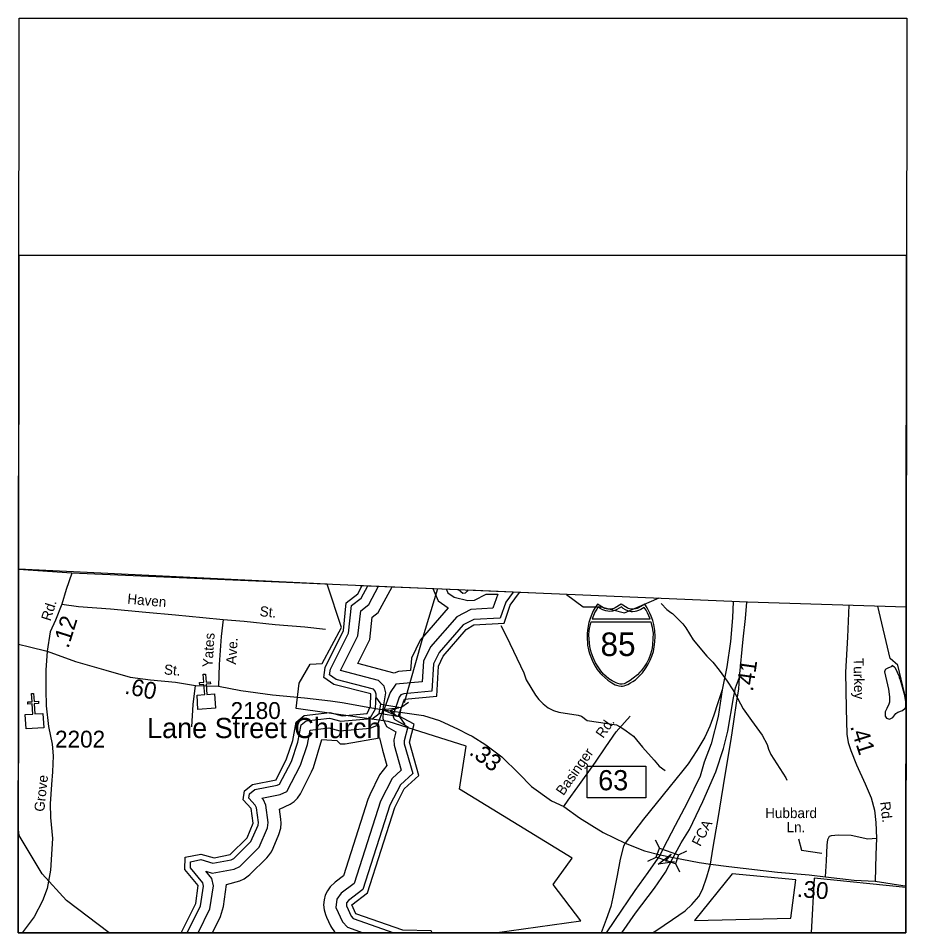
# Model space of a CAD drawing. Extents: x 1513414 to 1532852, y 643392 to 657912.
# Drawn here: x 1513414 to 1520009, y 643669 to 650461 of the extents above; entities that cross this region are included whole.
import ezdxf

# ---------------------------------------------------------------- set-up
doc = ezdxf.new("R2010")
doc.units = 0
doc.layers.add('Default', color=7, linetype='Continuous')

msp = doc.modelspace()

# ---------------------------------------------------------------- linework, layer by layer
at = {"layer": 'Default'}
for p, q in [((1520007.5, 648700.2), (1513418.3, 648700.2)), ((1516681.5, 646215.8), (1515951, 646246.8)), ((1517202.2, 646193.8), (1516751, 646212.9)), ((1516065.3, 645422.1), (1516105.4, 645366)), ((1516254.4, 645340.8), (1516310.5, 645380.9)), ((1516037.6, 645256.2), (1516093.8, 645296.3)), ((1516243, 645272.7), (1516283.1, 645216.6)), ((1518142.8, 644359.3), (1518172.9, 644297.2)), ((1518315.6, 644247.4), (1518377.7, 644277.5)), ((1518087.8, 644200.4), (1518149.8, 644230.5)), ((1518293, 644182.2), (1518323.2, 644120.2))]:
    msp.add_line(p, q, dxfattribs=at)
for points in [[(1513419.9, 650460.8), (1520009.1, 650460.8), (1520002.8, 643669.3), (1513413.6, 643669.3)], [(1517888.8, 645500.4), (1517898.3, 645501.3), (1517911.1, 645503.7), (1517923.4, 645507.8), (1517937.6, 645514), (1517958.4, 645525.6), (1517975.1, 645535.4), (1517994.5, 645548.4), (1518020.6, 645572.1), (1518046.6, 645599.5), (1518069.6, 645630.6), (1518087.9, 645659.6), (1518104, 645692.7), (1518117.4, 645723.6), (1518128.1, 645759), (1518135.1, 645793.2), (1518138.7, 645828.9), (1518141.1, 645868.5), (1518138.4, 645913), (1518130.6, 645958.6), (1518123.4, 645986.9), (1518112.3, 646020.9), (1518103.3, 646042.6), (1518082.5, 646081), (1518063.8, 646110.6), (1518036.5, 646091.4), (1518018.8, 646082), (1518007.9, 646077.1), (1517996.8, 646074.9), (1517976.3, 646072.4), (1517963.4, 646073), (1517951.4, 646075.7), (1517941.3, 646077.9), (1517933.1, 646082), (1517888.8, 646110.6), (1517844.6, 646082), (1517835.3, 646077.7), (1517825.8, 646075.7), (1517816.6, 646073.2), (1517801.5, 646072.4), (1517789.9, 646072.8), (1517778.1, 646074.9), (1517768.7, 646076.9), (1517758.2, 646082), (1517713, 646110.6), (1517695.3, 646084.9), (1517680.9, 646059.5), (1517665.5, 646023.5), (1517656, 645995.7), (1517649.1, 645972.8), (1517640.8, 645930.9), (1517636.5, 645894.3), (1517635.7, 645868.5), (1517640.5, 645804), (1517647.5, 645769.6), (1517654.7, 645741.8), (1517678.6, 645681.8), (1517696.5, 645648.2), (1517712, 645624), (1517733.5, 645596.8), (1517745.2, 645583.9), (1517790, 645544.7), (1517820, 645524.3), (1517843.9, 645511.4), (1517855.1, 645507.1), (1517872.7, 645502.2)], [(1517718.4, 646089.8), (1517707.4, 646072.9), (1517694.7, 646050.1), (1517684.6, 646026.4), (1517674.2, 646000.2), (1518105.8, 646000.1), (1518095.8, 646022.5), (1518085, 646045), (1518073.7, 646065.6), (1518060, 646085.5), (1518035.8, 646070.3), (1518018.2, 646061.9), (1518004, 646057), (1517992, 646054.3), (1517973.4, 646052.9), (1517965.1, 646053.4), (1517939.2, 646059.2), (1517921.6, 646066.4), (1517904.9, 646077.6), (1517891.4, 646090.3), (1517857.2, 646069.6), (1517842.1, 646062.9), (1517824.6, 646058.5), (1517805.5, 646056.1), (1517776.1, 646059.2), (1517753, 646067.2), (1517733.2, 646077.6)], [(1518108.4, 645978.8), (1518113, 645966.6), (1518119.3, 645939.6), (1518122.7, 645918.7), (1518126.1, 645894.7), (1518124.9, 645853.6), (1518122.9, 645811), (1518119, 645785.8), (1518113.8, 645762.9), (1518106.6, 645737.4), (1518095.1, 645703.6), (1518079.2, 645674.9), (1518059.3, 645643.1), (1518037.8, 645615.2), (1518028.5, 645603.7), (1518010.8, 645585), (1517978.6, 645559.1), (1517955, 645541.5), (1517926.9, 645524.9), (1517912.6, 645518.5), (1517895.9, 645515.1), (1517882.2, 645516), (1517865.6, 645520.4), (1517852.1, 645524.1), (1517822.7, 645540), (1517798.8, 645556), (1517759.1, 645588.6), (1517737.6, 645613.7), (1517717.6, 645643.1), (1517699.7, 645673.2), (1517680.6, 645712.9), (1517667.2, 645752.8), (1517657.4, 645795.8), (1517650.8, 645848.5), (1517650, 645880.5), (1517652, 645911.4), (1517654.9, 645927.5), (1517658.8, 645947.6), (1517666.7, 645978.6)], [(1514740.5, 645433.6), (1514797.3, 645437.5), (1514792.2, 645513.5), (1514760.3, 645511.3), (1514759.3, 645527.3), (1514791.2, 645529.4), (1514787.2, 645589.4), (1514803.2, 645590.5), (1514807.2, 645530.5), (1514839.1, 645532.6), (1514840.2, 645516.7), (1514808.2, 645514.5), (1514813.3, 645438.6), (1514870.8, 645442.3), (1514877.9, 645336.1), (1514747.6, 645327.4)], [(1513464.7, 645289.4), (1513521.5, 645293.3), (1513516.5, 645369.3), (1513484.5, 645367.1), (1513483.5, 645383.1), (1513515.4, 645385.2), (1513511.4, 645445.2), (1513527.4, 645446.3), (1513531.4, 645386.3), (1513563.3, 645388.4), (1513564.4, 645372.5), (1513532.4, 645370.3), (1513537.5, 645294.4), (1513595.1, 645298.1), (1513602.1, 645191.9), (1513471.8, 645183.2)], [(1516105.4, 645366), (1516254.5, 645341.1), (1516242.8, 645271.5), (1516093.8, 645296.3)], [(1516226, 645277.8), (1516114.6, 645327.3), (1516235.8, 645340.1), (1516174.8, 645317.8)], [(1517637.1, 644905.3), (1518072, 644905.3), (1518072, 644672.1), (1517637.1, 644672.1)], [(1518172.9, 644297.2), (1518315.7, 644247.7), (1518292.6, 644181), (1518149.8, 644230.5)], [(1518284.2, 644194.9), (1518163.3, 644178.9), (1518260, 644253.2), (1518219.6, 644202.3)]]:
    msp.add_lwpolyline(points, close=True, dxfattribs=at)
for points in [[(1513418.3, 648700.2), (1513413.6, 643669.3), (1520002.8, 643669.3), (1520007.5, 648700.2)], [(1515706.2, 646257.9), (1513416.1, 646369.7)], [(1515706.2, 646257.9), (1513416.1, 646369.7)], [(1520005, 646087.8), (1518827.8, 646124.9), (1515916.8, 646248.2), (1513810.1, 646340.9), (1513416.1, 646366.9)], [(1513810.6, 646340.9), (1513769.4, 646219.1), (1513736.4, 646110.1), (1513690.2, 645989.6), (1513650.6, 645903.7), (1513627.8, 645760.1)], [(1515451.4, 645097.8), (1515476.6, 645233.8), (1515535.6, 645281.8), (1515727.6, 645304.2), (1515818.6, 645279.4), (1516002.6, 645298.6), (1516028.6, 645350.7), (1516029.6, 645442.5), (1515755.6, 645513.7), (1515681.6, 645564.5), (1515691.6, 645639.7), (1515828.6, 645912.7), (1515848.6, 646119.1), (1515933.6, 646186.3), (1515965.7, 646248.1)], [(1516951.9, 643669.3), (1517589, 643756.4), (1517383.6, 644028.1), (1517525.8, 644222.3), (1516689.2, 644735.2), (1516739.5, 645055.8), (1516158.3, 645239), (1515476.3, 645335.2), (1515499.2, 645523), (1515581.6, 645665), (1515668.5, 645669.6), (1515813.1, 645935.4), (1515706.2, 646257.9)], [(1516951.9, 643669.3), (1517589, 643756.4), (1517383.6, 644028.1), (1517525.8, 644222.3), (1516689.2, 644735.2), (1516739.5, 645055.8), (1516158.3, 645239), (1515476.3, 645335.2), (1515499.2, 645523), (1515581.6, 645665), (1515668.5, 645669.6), (1515813.1, 645935.4), (1515706.2, 646257.9)], [(1515724.5, 645583.6), (1515730.4, 645627.8), (1515864.4, 645894.8), (1515886.7, 646098.3), (1515958.4, 646154.9), (1516007.6, 646246.4)], [(1515806.4, 645616.7), (1515935.5, 645873.8), (1515955.9, 646060), (1516015.5, 646107.1), (1516088.7, 646243.2)], [(1515933.3, 645668.5), (1516023.3, 645847.8), (1516041.4, 646012.6), (1516086.1, 646047.9), (1516188.9, 646239.1)], [(1516280.9, 645379.3), (1516413, 645840.9), (1516528, 646225.4)], [(1516280.9, 645379.3), (1516413, 645840.9), (1516528, 646225.4)], [(1516491.3, 646226.4), (1516529.5, 646133.9), (1516605.1, 646081.3)], [(1516590.6, 646222.2), (1516602.7, 646192.8), (1516648.5, 646161), (1516751.7, 646135.9), (1516800.6, 646138.7), (1516887.8, 646182.8), (1516973.7, 646184.1)], [(1517086.8, 646199), (1517033.2, 646124.5), (1516992.1, 646006), (1516794.5, 645995.5), (1516717.3, 645955.1), (1516537.3, 645750), (1516497.2, 645665.6), (1516483.5, 645462.8), (1516276.1, 645444.5), (1516253.9, 645435.3), (1516242, 645418.3), (1516197.9, 645294.2), (1516196.2, 645273.9), (1516204.9, 645255.2), (1516305, 645198.8), (1516278, 645093.9), (1516278.4, 645072.9), (1516342.2, 644850.9), (1516250.7, 644768.1), (1516172.8, 644616.3), (1515972.3, 643990.2), (1515864.5, 643908.3), (1515850.9, 643890.1), (1515849.2, 643869.5), (1515884.6, 643792.7), (1515900.5, 643775.5), (1516202.7, 643669.3)], [(1516973.7, 646184.1), (1516937.3, 646078.8), (1516774, 646070.2), (1516669.7, 646015.5), (1516473.5, 645792), (1516422.7, 645685.1), (1516412.4, 645532.5), (1516217.5, 645515.3)], [(1516316.8, 645084), (1516351.6, 645219.4), (1516235.6, 645280.9), (1516279.6, 645404.7), (1516521.5, 645426), (1516533.6, 645649.1), (1516567.6, 645723.9), (1516737.6, 645920.6), (1516796.6, 645955.6), (1517021.6, 645967.5), (1517065.7, 646101.1), (1517134.6, 646196.7)], [(1516751, 646212.9), (1516747, 646206), (1516730.9, 646189.9), (1516714.9, 646188.6), (1516681.5, 646215.8)], [(1516751, 646212.9), (1516747, 646206), (1516730.9, 646189.9), (1516714.9, 646188.6), (1516681.5, 646215.8)], [(1517483, 646180.7), (1517607.6, 646090.2), (1517740.6, 646090.8), (1517914.6, 646044.6), (1518170.7, 646155.4)], [(1513736.4, 646110.1), (1513859.7, 646092), (1514099.3, 646073.8), (1514360.9, 646050.9), (1514580.4, 646031), (1514784.1, 646011.3), (1514933.9, 645994.5)], [(1518186.2, 646115.5), (1518229.5, 646070.3), (1518257.2, 646048.4), (1518271.1, 646039.9), (1518348, 645962.9), (1518369.4, 645934.5), (1518424, 645845.6), (1518524.1, 645723.8), (1518569.6, 645678.6), (1518616.6, 645618.5), (1518675.2, 645536.9), (1518718.3, 645472.8), (1518734, 645447.9), (1518796.2, 645330.9), (1518856.9, 645246), (1518935.1, 645135.3), (1518972.1, 645068.1), (1518983.4, 645031.8)], [(1518720.9, 646129.4), (1518716.2, 646007), (1518700.6, 645831.4), (1518674.7, 645643), (1518639.9, 645472.4)], [(1518767.9, 645567.3), (1518794.2, 645850.5), (1518811.4, 646002.1), (1518821.6, 646125.1)], [(1519578.6, 646101.2), (1519568.8, 645863.7), (1519554, 645605), (1519559, 645334.9), (1519565.3, 645144.9), (1519574.3, 645082.7), (1519593.4, 645022.4), (1519636.1, 644915.2), (1519700, 644776.2), (1519744.3, 644671.5), (1519768.8, 644578.9), (1519779.4, 644488.9), (1519785.6, 644370.7), (1519779.2, 644247.9), (1519774.5, 644052.8)], [(1520004.4, 645396.3), (1519942.6, 645655.8), (1519885.6, 645706.2), (1519794.8, 646094.4)], [(1516605.1, 646081.3), (1516396, 645843), (1516332.2, 645708.8), (1516326, 645617.2), (1516235.7, 645609.2), (1516204.9, 645596.5)], [(1514933.9, 645994.5), (1514919.5, 645868.9), (1514905.9, 645661.1), (1514899.1, 645499.2)], [(1514933.9, 645994.5), (1515089.7, 645983.8), (1515321.2, 645959.5), (1515540.9, 645941.4), (1515694.6, 645924.7)], [(1516995.2, 645949.9), (1517037.9, 645869.5), (1517167.7, 645599.3), (1517182.9, 645546.5), (1517253.1, 645433.5), (1517278.7, 645401), (1517310.1, 645368.3), (1517347.6, 645339.7), (1517387.5, 645319.1), (1517427.3, 645308.5), (1517571, 645284.3), (1517594.8, 645276.4), (1517636.2, 645245.2), (1517853.9, 645213.7), (1517893.7, 645191.6), (1517927.3, 645168.7), (1517980.6, 645129.9), (1518047.4, 645046.5)], [(1513415.6, 645811.8), (1513496.3, 645792.8), (1513627.8, 645760.1)], [(1513627.8, 645760.1), (1513618.1, 645619.7), (1513618.1, 645474.1), (1513619.4, 645353.2), (1513638.9, 645201.1), (1513666.1, 645069.6), (1513673, 644983.4), (1513668.7, 644864.8), (1513659, 644769.8), (1513649.2, 644627.4), (1513653.1, 644524.1), (1513668.7, 644368.1), (1513653.3, 644132.7), (1513629.1, 643997), (1513592.6, 643905), (1513530.8, 643787.9), (1513441.7, 643669.3)], [(1513627.8, 645760.1), (1513838.4, 645684.4), (1514064.2, 645618.5), (1514243.3, 645567.2), (1514396, 645548.3), (1514581.6, 645531), (1514729.1, 645506.4), (1514899.1, 645499.2), (1515064.5, 645468.2), (1515302, 645436), (1515537.4, 645413.6), (1515731.1, 645392.1), (1515816.9, 645378.6), (1516024.2, 645340.8), (1516174.8, 645317.8)], [(1516087.2, 645542.2), (1515806.4, 645616.7)], [(1516204.9, 645596.5), (1515933.3, 645668.5)], [(1519897.6, 645654.2), (1519897.5, 645646), (1519869.3, 645634.3), (1519853.1, 645626.4), (1519849.2, 645622.4), (1519845, 645606.9), (1519874.8, 645478.3), (1519882, 645422.3), (1519881.3, 645382.1), (1519877, 645366.6), (1519860.6, 645334.1), (1519850.3, 645310.5), (1519849.6, 645278.5), (1519859.4, 645262.8), (1519881.4, 645255.7), (1519905.6, 645267.5), (1519928, 645297.5), (1519944.2, 645307), (1519978.5, 645320.2), (1519996.7, 645336.3), (1520002.8, 645346), (1520003.4, 645376.4), (1520001.4, 645384.6), (1519994.1, 645432.3), (1519964, 645544.6), (1519956.3, 645561.1), (1519956.5, 645569.3), (1519925.3, 645634), (1519919.6, 645641.5), (1519897.6, 645654.2)], [(1514668.3, 643669.3), (1514766.4, 643869), (1514788.2, 644015.5), (1514783.2, 644040.8), (1514690.9, 644151.9), (1514691.9, 644196.7), (1514767.9, 644212.3), (1514857.6, 644186.7), (1514993.6, 644209.9), (1515013.7, 644220.6), (1515140.7, 644346.1), (1515193.6, 644466.8), (1515196.2, 644487.5), (1515181.2, 644596.1), (1515172.2, 644616.3), (1515126, 644669.7), (1515130.8, 644701.6), (1515169.9, 644733.5), (1515334.9, 644764.2), (1515353.4, 644772.9), (1515441.3, 644941.6), (1515489.3, 645085.3), (1515513.2, 645212), (1515551.9, 645243.5), (1515724.6, 645263.6), (1515808.1, 645240.9), (1516006.8, 645258.9), (1516028.3, 645268), (1516064.4, 645332.8), (1516069.6, 645442.1), (1516064.2, 645462.5), (1516049.6, 645477.2), (1515772.5, 645550.7), (1515724.5, 645583.6)], [(1514749.1, 643669.3), (1514836.5, 643847.2), (1514861.8, 644017.3), (1514850.8, 644073), (1514806.9, 644125.8), (1514853.5, 644112.5), (1515017.4, 644140.4), (1515057.2, 644161.7), (1515201.6, 644304.3), (1515264.3, 644447.4), (1515269.3, 644488), (1515251.7, 644616.3), (1515234, 644655.7), (1515222.1, 644669.5), (1515357.3, 644694.6), (1515406.3, 644717.6), (1515508.3, 644913.2), (1515559.7, 645067), (1515579.6, 645172.5), (1515581.2, 645173.9), (1515719.1, 645189.9), (1515801.6, 645167.5), (1516024.7, 645187.7), (1516079.6, 645211.1), (1516120.2, 645318), (1516142.6, 645449.9), (1516129.3, 645499.9), (1516087.2, 645542.2)], [(1518276, 644227.4), (1518319.5, 644309.1), (1518335.4, 644335.7), (1518396.9, 644436.3), (1518496, 644645), (1518591.1, 644865), (1518649.5, 645037.3), (1518682.4, 645166.5), (1518723.7, 645413.3), (1518739.2, 645486.8), (1518767.9, 645567.3)], [(1518553.2, 644179), (1518569.6, 644289.7), (1518595.4, 644434.1), (1518607.7, 644502.2), (1518648.5, 644762.5), (1518685.2, 644988.6), (1518707, 645105.1), (1518726.1, 645238.5), (1518747.8, 645392.3), (1518762.8, 645477.6), (1518767.9, 645567.3)], [(1514701.7, 645198.8), (1514712.7, 645364.6), (1514729.1, 645506.4)], [(1516217.5, 645515.3), (1516174.1, 645453.3), (1516123.3, 645310.2), (1516119.2, 645260.2), (1516146.6, 645201.2), (1516217.3, 645161.4), (1516202.3, 645102.9), (1516202.9, 645061.7), (1516256.5, 644875.3), (1516189.7, 644815), (1516102.6, 644645.3), (1515907.6, 644036), (1515810.2, 643962), (1515777.4, 643917.9), (1515772.1, 643856), (1515820.9, 643750.1), (1515857.8, 643710.3), (1515974.6, 643669.3)], [(1518639.9, 645472.4), (1518606.9, 645377.5), (1518578.3, 645286.2), (1518547, 645204.5), (1518511.6, 645122.8), (1518451.7, 645023.4), (1518387.1, 644923.5), (1518346.3, 644874.5), (1518242.8, 644746.4), (1518055, 644513.2), (1517982.9, 644419.2), (1517919.7, 644334.4)], [(1518639.9, 645472.4), (1518610, 645274), (1518558.6, 645071.3), (1518506.6, 644935.4), (1518475.7, 644831.4), (1518380.3, 644634.2), (1518289.6, 644465.2), (1518230.2, 644352.2), (1518206.3, 644303.9), (1518179.8, 644246.6)], [(1516174.8, 645317.8), (1516247.6, 645306.7), (1516421, 645281.6), (1516540.5, 645245.3), (1516679.3, 645180.9), (1516756.7, 645141.9), (1516782.3, 645129), (1516885.2, 645064.5), (1517003.9, 644974.7), (1517130.1, 644852.7), (1517224.6, 644755.1), (1517370.9, 644648.7), (1517462.7, 644606.8), (1517580.9, 644521.6), (1517671.5, 644466.6), (1517756.7, 644414.3), (1517919.7, 644334.4)], [(1517462.7, 644606.8), (1517497, 644652.8), (1517568.7, 644751.8), (1517697.6, 644935.7), (1517775, 645050.6), (1517852.9, 645161.6), (1517954.9, 645277.6)], [(1514623.8, 643669.3), (1514730.6, 643886.7), (1514748.6, 644020.8), (1514650.6, 644137.7), (1514652.6, 644229.6), (1514769.6, 644253.4), (1514868.6, 644225.2), (1514985.6, 644249.1), (1515112.5, 644374.6), (1515156.6, 644482), (1515141.5, 644590.6), (1515083.6, 644657.4), (1515093.6, 644722.9), (1515152.6, 644770.9), (1515327.6, 644803.5), (1515405.6, 644959.5), (1515451.4, 645097.8)], [(1514855.8, 643669.3), (1514915.1, 643789.6), (1514938, 643864.7), (1514960, 644028.4), (1515057.1, 644053.5), (1515089.6, 644068.7), (1515120.8, 644090.6), (1515133.1, 644101.8), (1515257.9, 644225.1), (1515271.4, 644239.6), (1515293.3, 644271), (1515306.4, 644297.8), (1515348.1, 644399.4), (1515361.7, 644446.6), (1515364.9, 644482.7), (1515362.8, 644512.9), (1515352.5, 644586.4), (1515431.7, 644623.2), (1515461.4, 644644), (1515487.1, 644669.7), (1515508.5, 644700.3), (1515590.9, 644864.1), (1515604.1, 644895.6), (1515666.7, 645104.9), (1515778, 645096.4), (1515802, 645072.7), (1515819.9, 645071.1), (1515839.6, 645072.1), (1516095.7, 645117.7)], [(1516095.7, 645117.7), (1516116.9, 645024.5), (1516149.4, 644912.2), (1516096.2, 644840.8), (1516022.7, 644693.3), (1516009.2, 644659.6), (1515828.1, 644092.1), (1515765.7, 644044.9), (1515728.6, 644009.5), (1515708.3, 643980.5), (1515692.9, 643947.6), (1515683.5, 643912.5), (1515680.3, 643876.4), (1515683.5, 643840.2), (1515693.3, 643803.9), (1515701.6, 643784.2), (1515732.3, 643720.6), (1515739.2, 643707.4), (1515761, 643676.2), (1515768, 643669.3)], [(1516486.1, 643669.3), (1516477.6, 643684), (1516269.5, 643688.2), (1515920.5, 643810.1), (1515888.6, 643876.4), (1516006.6, 643966), (1516208.5, 644598.6), (1516277.6, 644738.4), (1516387.5, 644837.9), (1516316.8, 645084)], [(1518047.4, 645046.5), (1518134.2, 644951.2), (1518171.6, 644906.2), (1518217.1, 644874.1)], [(1518983.4, 645031.8), (1519000.8, 644993.6), (1519112.5, 644819.9), (1519118.3, 644803.4)], [(1514088.8, 643669.3), (1513771.6, 643909.3), (1513591.6, 644106.6), (1513420.5, 644392.3), (1513414.3, 644437)], [(1519405.7, 644083.4), (1519414.7, 644202.5), (1519418.6, 644318.5), (1519423.3, 644362.4), (1519435.6, 644386.1), (1519449.7, 644391.9), (1519499.8, 644397.3), (1519597.8, 644393.7), (1519719.5, 644367.6), (1519785.6, 644370.7)], [(1517919.7, 644334.4), (1517906.7, 644313), (1517882.2, 644215), (1517860.4, 644095.1), (1517826.4, 643932.7), (1517811.4, 643864.6), (1517777.4, 643767.9), (1517740, 643669.3)], [(1517919.7, 644334.4), (1518063.7, 644277.2), (1518179.8, 644246.6)], [(1519206.5, 644365.6), (1519229.2, 644283.5), (1519379.6, 644260.7)], [(1518179.8, 644246.6), (1518086.4, 644117.4), (1517990.2, 643982.7), (1517839.1, 643759.9), (1517777.3, 643669.3)], [(1517895.3, 643669.3), (1517996.4, 643814.1), (1518135.9, 643999.1), (1518218.3, 644120.1), (1518276, 644227.4)], [(1518179.8, 644246.6), (1518276, 644227.4)], [(1518276, 644227.4), (1518468.3, 644191.6), (1518553.2, 644179)], [(1518121.6, 643669.3), (1518145.5, 643684.4), (1518269.4, 643767.5), (1518363.3, 643832.9), (1518413.6, 643879.1), (1518465.3, 643937.7), (1518492.5, 643989.5), (1518526, 644085.5), (1518543.7, 644144), (1518553.2, 644179)], [(1518553.2, 644179), (1518689.5, 644161.4), (1519050.7, 644120.1), (1519286, 644099.8), (1519405.7, 644083.4), (1519619.5, 644059.9), (1519774.5, 644052.8)], [(1518714.1, 644105.6), (1518434.8, 643761.1), (1519147.7, 643776.4), (1519184.8, 644060.8), (1518714.1, 644105.6)], [(1518714.1, 644105.6), (1518434.8, 643761.1), (1519147.7, 643776.4), (1519184.8, 644060.8), (1518714.1, 644105.6)], [(1518714.1, 644105.6), (1518434.8, 643761.1), (1519147.7, 643776.4), (1519184.8, 644060.8), (1518714.1, 644105.6)], [(1518714.1, 644105.6), (1518434.8, 643761.1), (1519147.7, 643776.4), (1519184.8, 644060.8), (1518714.1, 644105.6)], [(1520003.1, 644004), (1519323.3, 644073.6), (1519300.5, 643669.3)], [(1520003.1, 644004), (1519323.3, 644073.6), (1519300.5, 643669.3)], [(1520003.1, 644004), (1519323.3, 644073.6), (1519300.5, 643669.3)], [(1520003.1, 644004), (1519323.3, 644073.6), (1519300.5, 643669.3)], [(1519774.5, 644052.8), (1519981.1, 644019.9), (1520003.1, 644018)], [(1519300.5, 643669.3), (1520002.8, 643669.3), (1520003.1, 644004)], [(1519300.5, 643669.3), (1520002.8, 643669.3), (1520003.1, 644004)], [(1519300.5, 643669.3), (1520002.8, 643669.3), (1520003.1, 644004)], [(1519300.5, 643669.3), (1520002.8, 643669.3), (1520003.1, 644004)]]:
    msp.add_lwpolyline(points, dxfattribs=at)

# ---------------------------------------------------------------- texts
for s, height, rotation, p in [('Haven', 75, 354.83638, (1514220.7, 646113)), ('Rd.', 75, 72.50344, (1513652.4, 645979.3)), ('St.', 75, 354.01104, (1515202.7, 646021.4)), ('.12', 125, 72.50344, (1513784.7, 645776.1)), ('Yates', 75, 86.25533, (1514855.1, 645638.4)), ('Ave.', 75, 86.25533, (1515030.3, 645659.2)), ('.41', 125, 81.76303, (1518866.6, 645456.6)), ('Turkey', 75, 271.05034, (1519613.9, 645709.2)), ('St.', 75, 354.65808, (1514492.4, 645588.7)), ('.60', 125, 348.20453, (1514198, 645446.3)), ('Rd.', 75, 54.96632, (1517755.4, 645108.4)), ('.41', 125, 287.59839, (1519588.3, 645201.4)), ('.33', 125, 322.66307, (1516754.3, 644998.3)), ('Basinger', 75, 54.95724, (1517460.3, 644682.9)), ('Grove', 75, 83.90792, (1513606, 644565.2)), ('Rd.', 75, 276.70717, (1519811.2, 644639.5)), ('FCA', 75, 62.56082, (1518475.9, 644305.1)), ('.30', 125, 355.24857, (1519191.7, 643935.6))]:
    msp.add_text(s, height=height, rotation=rotation, dxfattribs=at).set_placement(p)
for s, height, p in [('85', 175, (1517736, 645724.1)), ('2180', 125, (1514990.3, 645256.8)), ('Lane Street Church', 150, (1514369.6, 645114.7)), ('2202', 125, (1513686.5, 645044.6)), ('63', 150, (1517718.5, 644727)), ('Hubbard', 75, (1518958.3, 644520.6)), ('Ln.', 75, (1519117.2, 644415.8))]:
    msp.add_text(s, height=height, dxfattribs=at).set_placement(p)

doc.saveas('drawing.dxf')
